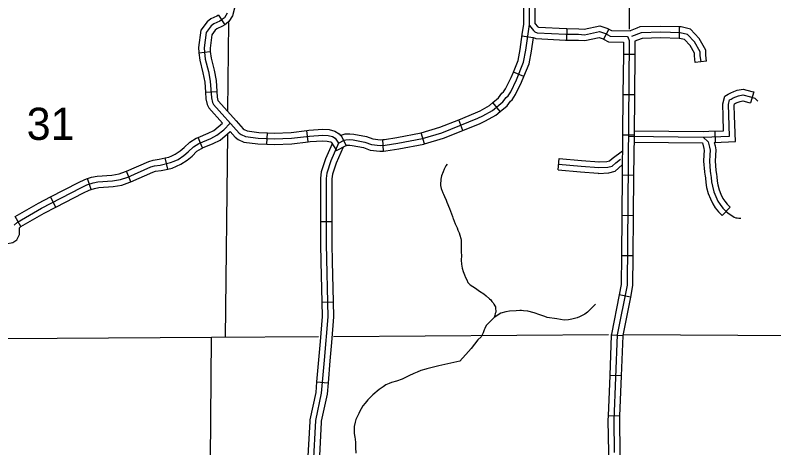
# Model space of a CAD drawing. Extents: x 1373862 to 1376999, y 1168398 to 1170455.
# Drawn here: x 1375607.7 to 1375806.5, y 1168765.8 to 1168879.3 of the extents above; entities that cross this region are included whole.
import ezdxf

# ---------------------------------------------------------------- set-up
doc = ezdxf.new("R2010")
doc.units = 0
for name, color, linetype in [('Level 32', 7, 'Continuous'), ('Level 35', 7, 'Continuous'), ('Level 4', 7, 'Continuous'), ('Level 45', 7, 'Continuous'), ('Level 5', 7, 'Continuous')]:
    doc.layers.add(name, color=color, linetype=linetype)

msp = doc.modelspace()

# ---------------------------------------------------------------- linework, layer by layer
at = {"layer": 'Level 32'}
for p, q in [((1375660.99, 1168879.27), (1375662.64, 1168876.77)), ((1375781.7, 1168876.19), (1375781.63, 1168873.19)), ((1375752.21, 1168875.76), (1375752.18, 1168872.76)), ((1375763.27, 1168875.64), (1375761.82, 1168873)), ((1375743.4, 1168873.31), (1375740.44, 1168873.75)), ((1375655.85, 1168869.37), (1375658.83, 1168869.74)), ((1375770.04, 1168868.94), (1375767.04, 1168868.96)), ((1375788.86, 1168867.24), (1375785.89, 1168866.85)), ((1375741.01, 1168863.23), (1375738.23, 1168864.37)), ((1375657.58, 1168859.07), (1375660.57, 1168859.27)), ((1375769.94, 1168858.38), (1375766.94, 1168858.4)), ((1375734.81, 1168854.04), (1375732.89, 1168856.34)), ((1375725.03, 1168849.07), (1375723.92, 1168851.86)), ((1375673.7, 1168845.43), (1375673.84, 1168848.42)), ((1375684.48, 1168846.06), (1375684.1, 1168849.03)), ((1375714.96, 1168845.53), (1375714.09, 1168848.4)), ((1375656.83, 1168844.46), (1375655.69, 1168847.23)), ((1375694.47, 1168845.11), (1375693.11, 1168847.78)), ((1375704.22, 1168843.65), (1375704.06, 1168846.65)), ((1375769.84, 1168847.82), (1375766.84, 1168847.84)), ((1375647.74, 1168838.94), (1375647.05, 1168841.86)), ((1375638.07, 1168835.6), (1375636.87, 1168838.35)), ((1375627.64, 1168833.57), (1375626.69, 1168836.41)), ((1375769.74, 1168837.26), (1375766.74, 1168837.29)), ((1375618.41, 1168828.96), (1375617.02, 1168831.63)), ((1375609.24, 1168823.85), (1375607.74, 1168826.45)), ((1375769.65, 1168826.7), (1375766.65, 1168826.73)), ((1375769.55, 1168816.14), (1375766.55, 1168816.17)), ((1375768.88, 1168805.36), (1375765.94, 1168805.94)), ((1375766.88, 1168795.23), (1375763.88, 1168795.35)), ((1375766.46, 1168784.68), (1375763.46, 1168784.8)), ((1375766.03, 1168774.12), (1375763.03, 1168774.25))]:
    msp.add_line(p, q, dxfattribs=at)
for points in [[(1375732.81, 1168854.28), (1375735.49, 1168856.53), (1375736.37, 1168857.72), (1375736.85, 1168858.1), (1375737.54, 1168859.21), (1375739.04, 1168862.31), (1375740.93, 1168866.93), (1375741.49, 1168870.06), (1375742.48, 1168876.8), (1375742.47, 1168889.71)], [(1375665.29, 1168887.95), (1375665.21, 1168881.1), (1375664.7, 1168879.13), (1375663.69, 1168877.59), (1375662.97, 1168876.98), (1375662.64, 1168876.77)], [(1375740.56, 1168874.23), (1375740.95, 1168876.91), (1375740.94, 1168884.53)], [(1375743.95, 1168877.02), (1375743.94, 1168884.54)], [(1375660.99, 1168879.27), (1375660.6, 1168879.01), (1375659.02, 1168878.28), (1375657.99, 1168877.52), (1375656.36, 1168875.32), (1375655.78, 1168870.78), (1375655.84, 1168869.47), (1375655.85, 1168869.37)], [(1375663.28, 1168879.76), (1375662.53, 1168878.61), (1375662.05, 1168878.21), (1375661.31, 1168877.72), (1375659.78, 1168877.01), (1375659.04, 1168876.46), (1375657.77, 1168874.75), (1375657.26, 1168870.72), (1375657.31, 1168869.6), (1375657.54, 1168867.72), (1375658.37, 1168864.5), (1375658.86, 1168861.93), (1375659.16, 1168857.57), (1375659.41, 1168856.37), (1375659.71, 1168855.81), (1375666.39, 1168848.37), (1375666.9, 1168847.99), (1375668.08, 1168847.44), (1375671.43, 1168847), (1375675.62, 1168846.81), (1375680.12, 1168846.99), (1375684.83, 1168847.59), (1375688.35, 1168847.83), (1375689.73, 1168847.74), (1375690.9, 1168847.45), (1375691.54, 1168847.06), (1375692.43, 1168845.72), (1375693.95, 1168846.49), (1375694.39, 1168846.62), (1375695.41, 1168846.66), (1375696.25, 1168846.59), (1375699.34, 1168845.99), (1375701.06, 1168845.37), (1375703.35, 1168845.08), (1375704.67, 1168845.15), (1375707.97, 1168845.68), (1375714.43, 1168846.91), (1375719.47, 1168848.43), (1375728.96, 1168852.23), (1375730.23, 1168852.84), (1375732.81, 1168854.28)], [(1375662.64, 1168876.77), (1375662.06, 1168876.39), (1375660.56, 1168875.69), (1375660.13, 1168875.37), (1375659.24, 1168874.16), (1375658.79, 1168870.65), (1375658.83, 1168869.72)], [(1375742.44, 1168876.55), (1375743.47, 1168875.25), (1375743.85, 1168874.91), (1375744.48, 1168874.67), (1375751.97, 1168874.29), (1375755.32, 1168874.26), (1375756.86, 1168874.15), (1375760.76, 1168874.96), (1375762.37, 1168874.45), (1375763.59, 1168873.78), (1375768.04, 1168873.71), (1375768.22, 1168873.59), (1375768.6, 1168872.66), (1375768.01, 1168808.52), (1375765.42, 1168795.44)], [(1375743.95, 1168877.02), (1375744.55, 1168876.26), (1375744.63, 1168876.19), (1375744.78, 1168876.13), (1375752.02, 1168875.76), (1375752.21, 1168875.76)], [(1375752.21, 1168875.76), (1375755.38, 1168875.73), (1375756.76, 1168875.63), (1375760.84, 1168876.48), (1375762.95, 1168875.81), (1375763.27, 1168875.64)], [(1375781.7, 1168876.19), (1375776.87, 1168876.29), (1375771.38, 1168876.17), (1375770.6, 1168875.87)], [(1375788.86, 1168867.24), (1375788.66, 1168868.8), (1375788.66, 1168870.1), (1375786.94, 1168873.14), (1375784.62, 1168875.6), (1375782.15, 1168876.18), (1375781.7, 1168876.19)], [(1375738.23, 1168864.37), (1375739.45, 1168867.36), (1375739.98, 1168870.31), (1375740.56, 1168874.23)], [(1375763.27, 1168875.64), (1375763.98, 1168875.24), (1375768.81, 1168875.17)], [(1375770.6, 1168875.87), (1375768.81, 1168875.17)], [(1375787.38, 1168867.04), (1375787.16, 1168868.7), (1375787.16, 1168869.7), (1375785.72, 1168872.25), (1375783.84, 1168874.24), (1375781.96, 1168874.68), (1375776.87, 1168874.79), (1375771.67, 1168874.68), (1375769.14, 1168873.69)], [(1375741.01, 1168863.23), (1375742.35, 1168866.52), (1375742.94, 1168869.82), (1375743.47, 1168873.42)], [(1375743.47, 1168873.42), (1375744.16, 1168873.16), (1375751.92, 1168872.76), (1375752.18, 1168872.76)], [(1375752.18, 1168872.76), (1375755.25, 1168872.73), (1375756.96, 1168872.61), (1375760.68, 1168873.38), (1375761.76, 1168873.04), (1375761.82, 1168873)], [(1375761.82, 1168873), (1375763.19, 1168872.26), (1375767.07, 1168872.2), (1375767.04, 1168868.96)], [(1375770.07, 1168872.45), (1375770.04, 1168868.94)], [(1375771.69, 1168873.08), (1375770.07, 1168872.45)], [(1375781.63, 1168873.19), (1375776.87, 1168873.29), (1375771.97, 1168873.19), (1375771.69, 1168873.08)], [(1375785.89, 1168866.85), (1375785.66, 1168868.61), (1375785.66, 1168869.31), (1375784.5, 1168871.35), (1375783.06, 1168872.88), (1375781.77, 1168873.18), (1375781.63, 1168873.19)], [(1375655.85, 1168869.37), (1375656.09, 1168867.44), (1375656.93, 1168864.17), (1375657.4, 1168861.74), (1375657.58, 1168859.07)], [(1375658.83, 1168869.74), (1375659.05, 1168868), (1375659.86, 1168864.83), (1375660.38, 1168862.13), (1375660.57, 1168859.27)], [(1375767.04, 1168868.96), (1375766.94, 1168858.4)], [(1375770.04, 1168868.94), (1375769.94, 1168858.38)], [(1375732.89, 1168856.34), (1375734.37, 1168857.58), (1375735.25, 1168858.78), (1375735.69, 1168859.13), (1375736.2, 1168859.95), (1375737.64, 1168862.93), (1375738.23, 1168864.37)], [(1375734.81, 1168854.04), (1375736.58, 1168855.51), (1375737.44, 1168856.69), (1375737.96, 1168857.11), (1375738.83, 1168858.5), (1375740.38, 1168861.71), (1375741.01, 1168863.23)], [(1375657.58, 1168859.07), (1375657.69, 1168857.37), (1375658.01, 1168855.86), (1375658.5, 1168854.95), (1375662.08, 1168850.96)], [(1375660.57, 1168859.27), (1375660.67, 1168857.78), (1375660.86, 1168856.9), (1375660.97, 1168856.7), (1375665.59, 1168851.55)], [(1375766.94, 1168858.4), (1375766.84, 1168847.84)], [(1375769.94, 1168858.38), (1375769.84, 1168847.82)], [(1375723.92, 1168851.86), (1375728.34, 1168853.63), (1375729.53, 1168854.2), (1375731.94, 1168855.55), (1375732.89, 1168856.34)], [(1375725.03, 1168849.07), (1375729.55, 1168850.88), (1375730.91, 1168851.53), (1375733.65, 1168853.07), (1375734.81, 1168854.04)], [(1375607.5, 1168824.23), (1375608.32, 1168825.02), (1375614.62, 1168828.65), (1375624.98, 1168834.04), (1375626.55, 1168834.76), (1375628.15, 1168835.29), (1375629.43, 1168835.56), (1375633.25, 1168835.83), (1375635.32, 1168836.16), (1375637.23, 1168836.84), (1375643.26, 1168839.49), (1375644.22, 1168839.8), (1375645.68, 1168839.97), (1375648.4, 1168840.61), (1375649.42, 1168841), (1375650.4, 1168841.47), (1375651.91, 1168842.44), (1375653.07, 1168843.43), (1375654.42, 1168844.79), (1375655.88, 1168845.66), (1375658.95, 1168846.93), (1375660.59, 1168847.78), (1375662.38, 1168849.24), (1375664.07, 1168850.95)], [(1375655.69, 1168847.23), (1375658.31, 1168848.31), (1375659.75, 1168849.06), (1375662.08, 1168850.96)], [(1375665.59, 1168851.55), (1375667.43, 1168849.5), (1375667.68, 1168849.31), (1375668.51, 1168848.92), (1375671.56, 1168848.53), (1375673.84, 1168848.42)], [(1375714.09, 1168848.4), (1375718.96, 1168849.87), (1375723.92, 1168851.86)], [(1375656.83, 1168844.46), (1375659.57, 1168845.59), (1375661.4, 1168846.54), (1375663.37, 1168848.15), (1375664.02, 1168848.8)], [(1375664.02, 1168848.8), (1375665.39, 1168847.27), (1375666.14, 1168846.72), (1375667.67, 1168846.01), (1375671.3, 1168845.53), (1375673.7, 1168845.43)], [(1375673.84, 1168848.42), (1375675.62, 1168848.34), (1375680, 1168848.51), (1375684.1, 1168849.03)], [(1375684.1, 1168849.03), (1375684.68, 1168849.11), (1375688.34, 1168849.36), (1375689.97, 1168849.26), (1375691.49, 1168848.88), (1375692.62, 1168848.18), (1375692.95, 1168847.7), (1375693.11, 1168847.78)], [(1375704.06, 1168846.65), (1375704.51, 1168846.67), (1375707.71, 1168847.18), (1375714.07, 1168848.4), (1375714.09, 1168848.4)], [(1375714.96, 1168845.53), (1375719.96, 1168847.04), (1375725.03, 1168849.07)], [(1375647.05, 1168841.86), (1375647.95, 1168842.08), (1375648.82, 1168842.41), (1375649.65, 1168842.81), (1375651, 1168843.67), (1375652.03, 1168844.56), (1375653.47, 1168846), (1375655.19, 1168847.03), (1375655.69, 1168847.23)], [(1375684.48, 1168846.06), (1375684.97, 1168846.12), (1375688.35, 1168846.36), (1375689.5, 1168846.28), (1375690.32, 1168846.08), (1375690.49, 1168845.97), (1375691.93, 1168843.81), (1375694.47, 1168845.11)], [(1375693.11, 1168847.78), (1375693.39, 1168847.92), (1375694.14, 1168848.13), (1375695.44, 1168848.2), (1375696.46, 1168848.11), (1375699.75, 1168847.47), (1375701.42, 1168846.86), (1375703.4, 1168846.61), (1375704.06, 1168846.65)], [(1375766.84, 1168847.84), (1375766.74, 1168837.29)], [(1375769.84, 1168847.82), (1375769.74, 1168837.26)], [(1375647.74, 1168838.94), (1375648.84, 1168839.2), (1375650, 1168839.65), (1375651.12, 1168840.18), (1375652.8, 1168841.26), (1375654.07, 1168842.35), (1375655.33, 1168843.62), (1375656.54, 1168844.34), (1375656.83, 1168844.46)], [(1375673.7, 1168845.43), (1375675.61, 1168845.34), (1375680.24, 1168845.52), (1375684.48, 1168846.06)], [(1375694.47, 1168845.11), (1375694.49, 1168845.11), (1375694.62, 1168845.15), (1375695.38, 1168845.19), (1375696.04, 1168845.13), (1375698.94, 1168844.57), (1375700.72, 1168843.92), (1375703.3, 1168843.6), (1375704.22, 1168843.65)], [(1375704.22, 1168843.65), (1375704.83, 1168843.69), (1375708.23, 1168844.23), (1375714.78, 1168845.48), (1375714.96, 1168845.53)], [(1375636.87, 1168838.35), (1375642.72, 1168840.92), (1375643.9, 1168841.3), (1375645.42, 1168841.48), (1375647.05, 1168841.86)], [(1375626.69, 1168836.41), (1375627.75, 1168836.77), (1375629.22, 1168837.08), (1375633.08, 1168837.35), (1375634.94, 1168837.65), (1375636.67, 1168838.26), (1375636.87, 1168838.35)], [(1375638.07, 1168835.6), (1375643.79, 1168838.11), (1375644.54, 1168838.35), (1375645.94, 1168838.52), (1375647.74, 1168838.94)], [(1375617.02, 1168831.63), (1375624.31, 1168835.42), (1375625.99, 1168836.18), (1375626.69, 1168836.41)], [(1375766.74, 1168837.29), (1375766.65, 1168826.73)], [(1375769.74, 1168837.26), (1375769.65, 1168826.7)], [(1375627.64, 1168833.57), (1375628.54, 1168833.87), (1375629.64, 1168834.1), (1375633.43, 1168834.36), (1375635.68, 1168834.73), (1375637.78, 1168835.47), (1375638.07, 1168835.6)], [(1375618.41, 1168828.96), (1375625.62, 1168832.72), (1375627.09, 1168833.38), (1375627.64, 1168833.57)], [(1375607.74, 1168826.45), (1375613.88, 1168829.99), (1375617.02, 1168831.63)], [(1375609.24, 1168823.85), (1375615.33, 1168827.36), (1375618.41, 1168828.96)], [(1375766.65, 1168826.73), (1375766.55, 1168816.17)], [(1375769.65, 1168826.7), (1375769.55, 1168816.14)], [(1375603.79, 1168817.49), (1375603.93, 1168817.75), (1375604.64, 1168818.75), (1375605.28, 1168819.31), (1375607.17, 1168819.64), (1375608.18, 1168820.33), (1375608.88, 1168821.79), (1375608.84, 1168823.4), (1375608.86, 1168823.49), (1375609.21, 1168823.83), (1375609.24, 1168823.85)], [(1375766.55, 1168816.17), (1375766.48, 1168808.68), (1375765.94, 1168805.94)], [(1375769.55, 1168816.14), (1375769.48, 1168808.37), (1375768.88, 1168805.36)], [(1375765.94, 1168805.94), (1375763.9, 1168795.62), (1375763.88, 1168795.35)], [(1375768.88, 1168805.36), (1375766.88, 1168795.27), (1375766.88, 1168795.23)], [(1375763.88, 1168795.35), (1375763.46, 1168784.8)], [(1375765.42, 1168795.44), (1375764.51, 1168773.11), (1375764.67, 1168764.64)], [(1375766.88, 1168795.23), (1375766.46, 1168784.68)], [(1375763.46, 1168784.8), (1375763.03, 1168774.25)], [(1375766.46, 1168784.68), (1375766.03, 1168774.12)], [(1375763.03, 1168774.25), (1375762.99, 1168773.13), (1375763.15, 1168764.63), (1375763.14, 1168763.64)], [(1375766.03, 1168774.12), (1375765.99, 1168773.09), (1375766.15, 1168764.65), (1375766.14, 1168763.62)]]:
    msp.add_lwpolyline(points, dxfattribs=at)
at = {"layer": 'Level 35'}
for points in [[(1375720.87, 1168840.23), (1375720.57, 1168839.77), (1375720.13, 1168838.9), (1375719.82, 1168838.22), (1375719.43, 1168837.11), (1375719.26, 1168836.28), (1375719.17, 1168834.81), (1375719.18, 1168834.61), (1375719.3, 1168833.85), (1375719.57, 1168833.12), (1375719.7, 1168832.94), (1375719.75, 1168832.66), (1375719.92, 1168832.33), (1375720.2, 1168831.75), (1375720.62, 1168830.75), (1375720.79, 1168830.21), (1375721.49, 1168828.61), (1375722.25, 1168826.49), (1375722.38, 1168826.15), (1375722.45, 1168825.95), (1375722.69, 1168825.3), (1375722.98, 1168824.61), (1375723.19, 1168824.19), (1375723.34, 1168823.9), (1375723.5, 1168823.54), (1375723.72, 1168822.91), (1375724.01, 1168822.19), (1375724.21, 1168821.64), (1375724.48, 1168820.68), (1375724.59, 1168820.31), (1375724.6, 1168820.05), (1375724.56, 1168819.38), (1375724.56, 1168818.32), (1375724.56, 1168817.18), (1375724.61, 1168816.23), (1375724.53, 1168815.03), (1375724.63, 1168813.97), (1375724.83, 1168812.97), (1375725.12, 1168812.06), (1375725.41, 1168811.22), (1375725.72, 1168810.47), (1375726.02, 1168809.86), (1375726.34, 1168809.23), (1375726.91, 1168808.59)], [(1375726.91, 1168808.59), (1375728.28, 1168807.69), (1375728.63, 1168807.4), (1375729, 1168807.15), (1375729.33, 1168806.91), (1375730.48, 1168806.2), (1375731.13, 1168805.66), (1375731.98, 1168804.93), (1375732.29, 1168804.64), (1375732.62, 1168804.25), (1375732.98, 1168803.82), (1375733.15, 1168803.49), (1375733.37, 1168803.05), (1375733.53, 1168802.84), (1375733.59, 1168802.32), (1375733.63, 1168801.8), (1375733.6, 1168801.39), (1375733.51, 1168801.07), (1375733.37, 1168800.56), (1375733.19, 1168800.04)], [(1375759.76, 1168803.53), (1375759.6, 1168803.36), (1375759, 1168802.7), (1375758.3, 1168802.01), (1375757.66, 1168801.45), (1375756.97, 1168800.92), (1375755.57, 1168800.17), (1375754.92, 1168799.93), (1375754.28, 1168799.74), (1375753.52, 1168799.54), (1375752.7, 1168799.37), (1375751.54, 1168799.33), (1375749.66, 1168799.68), (1375747.12, 1168799.98), (1375746.47, 1168800.24), (1375745.2, 1168800.75), (1375743.64, 1168801.26), (1375742.06, 1168801.63), (1375740.85, 1168801.77), (1375740.38, 1168801.81), (1375739.9, 1168801.83), (1375739, 1168801.8), (1375737.25, 1168801.66), (1375736.29, 1168801.47), (1375734.98, 1168801.12), (1375733.19, 1168800.04), (1375731.07, 1168797.89), (1375730.72, 1168797.12), (1375730.59, 1168796.79), (1375730.31, 1168795.98), (1375729.77, 1168794.98), (1375728.91, 1168794.15), (1375727.16, 1168791.92), (1375725.79, 1168790.29), (1375724.9, 1168789.35), (1375724.18, 1168788.58)], [(1375724.18, 1168788.58), (1375718.72, 1168787.33), (1375716.27, 1168786.73), (1375715.55, 1168786.56), (1375715.29, 1168786.5), (1375713.97, 1168786.1), (1375713.05, 1168785.71), (1375712.14, 1168785.31), (1375710.82, 1168784.73), (1375709.84, 1168784.2), (1375709.08, 1168783.84), (1375707.61, 1168783.36), (1375706.35, 1168782.93), (1375705.73, 1168782.71), (1375704.87, 1168782.33), (1375704.13, 1168781.87), (1375703.1, 1168781.18), (1375701.46, 1168779.74), (1375700.6, 1168778.95), (1375700.12, 1168778.43), (1375699.4, 1168777.55), (1375698.82, 1168776.85), (1375698.38, 1168776.1), (1375698.04, 1168775.5), (1375697.72, 1168774.84), (1375696.97, 1168773.28), (1375696.79, 1168772.58), (1375696.53, 1168771.42), (1375696.55, 1168770.71), (1375696.54, 1168769.57), (1375696.72, 1168768.65), (1375696.82, 1168768.09), (1375696.88, 1168767.25), (1375696.91, 1168765.93), (1375696.95, 1168764.43)]]:
    msp.add_lwpolyline(points, dxfattribs=at)
at = {"layer": 'Level 4'}
for points in [[(1375687.15, 1168794.93), (1375659.21, 1168794.75), (1375591.7, 1168794.35)], [(1375763.16, 1168795.43), (1375691.09, 1168794.96)], [(1375881.05, 1168794.75), (1375871.72, 1168794.83), (1375767.06, 1168795.43)]]:
    msp.add_lwpolyline(points, dxfattribs=at)
at = {"layer": 'Level 45'}
for p, q in [((1375801.18, 1168859.13), (1375800.32, 1168856.25)), ((1375790.97, 1168848.84), (1375791.09, 1168845.84)), ((1375749.93, 1168838.74), (1375750.19, 1168841.73)), ((1375794.98, 1168828.92), (1375792.88, 1168826.78)), ((1375687.7, 1168825.2), (1375690.7, 1168825.2)), ((1375688.07, 1168804.05), (1375691.07, 1168804.13)), ((1375686.71, 1168783.16), (1375689.7, 1168782.9))]:
    msp.add_line(p, q, dxfattribs=at)
for points in [[(1375768.37, 1168847.52), (1375787.99, 1168847.31), (1375794.84, 1168847.58), (1375794.54, 1168855.88), (1375794.88, 1168857.07), (1375795.24, 1168857.28), (1375795.79, 1168857.57), (1375796.53, 1168857.89), (1375797.2, 1168858.14), (1375798.38, 1168858.35), (1375800.33, 1168857.84), (1375801.52, 1168857.48), (1375802.3, 1168856.7)], [(1375793.18, 1168852.73), (1375793.06, 1168856.06), (1375793.62, 1168858.05), (1375794.52, 1168858.57), (1375795.16, 1168858.9), (1375795.98, 1168859.25), (1375796.82, 1168859.57), (1375798.44, 1168859.85), (1375800.73, 1168859.26), (1375801.18, 1168859.13)], [(1375796.18, 1168852.84), (1375796.08, 1168855.7), (1375796.18, 1168856.05), (1375796.45, 1168856.19), (1375797.1, 1168856.47), (1375797.61, 1168856.66), (1375798.32, 1168856.78), (1375799.92, 1168856.37), (1375800.32, 1168856.25)], [(1375789.43, 1168848.84), (1375793.31, 1168848.99), (1375793.18, 1168852.73)], [(1375790.82, 1168845.89), (1375796.42, 1168846.11), (1375796.18, 1168852.84)], [(1375769.85, 1168848.98), (1375778.94, 1168848.88)], [(1375778.94, 1168848.88), (1375787.97, 1168848.78), (1375789.43, 1168848.84)], [(1375787.99, 1168847.31), (1375789.25, 1168846.03), (1375789.62, 1168844.67), (1375789.76, 1168843.85), (1375789.68, 1168842.54), (1375789.57, 1168840.98), (1375789.78, 1168838.41), (1375789.91, 1168837.79), (1375790.05, 1168836.71), (1375790.15, 1168835.57), (1375790.35, 1168834.43), (1375790.74, 1168832.99), (1375791.25, 1168831.72), (1375791.83, 1168830.5), (1375792.37, 1168829.63), (1375793.11, 1168828.7), (1375793.98, 1168827.84), (1375794.8, 1168827.19), (1375795.47, 1168826.72), (1375796.08, 1168826.35), (1375796.48, 1168826.16), (1375796.86, 1168826.11), (1375797.28, 1168826.08), (1375797.78, 1168826.08)], [(1375690.76, 1168845.57), (1375689.02, 1168841.58), (1375687.9, 1168838.2), (1375687.7, 1168836.52), (1375687.7, 1168835.76)], [(1375692.43, 1168845.72), (1375690.4, 1168841.06), (1375689.34, 1168837.88), (1375689.17, 1168836.44), (1375689.18, 1168819.24), (1375689.63, 1168800.19), (1375688.67, 1168788.79)], [(1375693.65, 1168844.69), (1375691.83, 1168840.51), (1375690.84, 1168837.55), (1375690.7, 1168836.35), (1375690.7, 1168835.76)], [(1375769.83, 1168845.98), (1375778.91, 1168845.88)], [(1375778.91, 1168845.88), (1375787.74, 1168845.78)], [(1375787.74, 1168845.78), (1375788.13, 1168844.34), (1375788.22, 1168843.77), (1375788.16, 1168842.64), (1375788.04, 1168840.97), (1375788.26, 1168838.19), (1375788.4, 1168837.53), (1375788.45, 1168837.16)], [(1375790.82, 1168845.89), (1375791.06, 1168844.98), (1375791.24, 1168843.93), (1375791.15, 1168842.45), (1375791.05, 1168840.98), (1375791.24, 1168838.62), (1375791.36, 1168838.04), (1375791.43, 1168837.55)], [(1375760.64, 1168840.81), (1375762.75, 1168840.9), (1375763.39, 1168841.07), (1375764.11, 1168841.72), (1375766.8, 1168843.68)], [(1375750.06, 1168840.24), (1375755.95, 1168839.72), (1375760.61, 1168839.31), (1375762.98, 1168839.41), (1375764.12, 1168839.72), (1375765.05, 1168840.55), (1375766.33, 1168841.48)], [(1375750.19, 1168841.73), (1375756.09, 1168841.21), (1375760.71, 1168840.8)], [(1375749.93, 1168838.74), (1375755.82, 1168838.22), (1375760.45, 1168837.81)], [(1375760.45, 1168837.81), (1375760.57, 1168837.8), (1375763.22, 1168837.92), (1375764.86, 1168838.36), (1375766.77, 1168840.07)], [(1375788.45, 1168837.16), (1375788.53, 1168836.54), (1375788.64, 1168835.37), (1375788.86, 1168834.1), (1375789.29, 1168832.51), (1375789.85, 1168831.1), (1375790.49, 1168829.77), (1375791.12, 1168828.75), (1375791.97, 1168827.68), (1375792.88, 1168826.78)], [(1375791.43, 1168837.55), (1375791.51, 1168836.87), (1375791.61, 1168835.76), (1375791.79, 1168834.75), (1375792.14, 1168833.46), (1375792.6, 1168832.31), (1375793.12, 1168831.21), (1375793.58, 1168830.48), (1375794.2, 1168829.69), (1375794.98, 1168828.92)], [(1375687.7, 1168835.76), (1375687.7, 1168825.2)], [(1375690.7, 1168835.76), (1375690.7, 1168825.2)], [(1375687.7, 1168825.2), (1375687.7, 1168819.23), (1375687.81, 1168814.61)], [(1375690.7, 1168825.2), (1375690.7, 1168819.26), (1375690.81, 1168814.68)], [(1375687.81, 1168814.61), (1375688.07, 1168804.05)], [(1375690.81, 1168814.68), (1375691.07, 1168804.13)], [(1375688.07, 1168804.05), (1375688.16, 1168800.24), (1375687.6, 1168793.68)], [(1375691.07, 1168804.13), (1375691.16, 1168800.15), (1375690.59, 1168793.42)], [(1375687.6, 1168793.68), (1375687.2, 1168788.91), (1375686.71, 1168783.16)], [(1375690.59, 1168793.42), (1375690.19, 1168788.66), (1375689.7, 1168782.9)], [(1375688.67, 1168788.79), (1375687.93, 1168780.16), (1375686.4, 1168773), (1375685.79, 1168761.66)], [(1375686.71, 1168783.16), (1375686.48, 1168780.38), (1375684.94, 1168773.19), (1375684.91, 1168772.72)], [(1375689.7, 1168782.9), (1375689.45, 1168779.93), (1375687.92, 1168772.8), (1375687.91, 1168772.56)], [(1375684.91, 1168772.72), (1375684.35, 1168762.18)], [(1375687.91, 1168772.56), (1375687.34, 1168762.02)]]:
    msp.add_lwpolyline(points, dxfattribs=at)
at = {"layer": 'Level 5'}
for points in [[(1375768.63, 1168875.61), (1375768.86, 1168901.09), (1375769.09, 1168923.56)], [(1375663.64, 1168877.35), (1375663.38, 1168854.24)], [(1375663.32, 1168848.04), (1375662.72, 1168794.77)], [(1375658.32, 1168688.01), (1375659.21, 1168794.75)]]:
    msp.add_lwpolyline(points, dxfattribs=at)

# ---------------------------------------------------------------- texts
msp.add_text('31', height=8.44, dxfattribs=at).set_placement((1375610.75, 1168846.57))

doc.saveas('drawing.dxf')
